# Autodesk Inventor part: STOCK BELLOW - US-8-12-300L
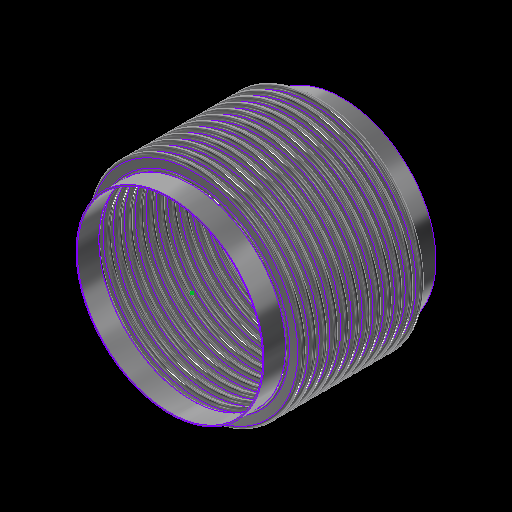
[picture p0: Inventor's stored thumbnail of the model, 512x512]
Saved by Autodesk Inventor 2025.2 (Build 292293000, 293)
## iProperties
Category: 22 GA (0.030 THICK)
RuleStatus: InUse
Created: 2024-01
Part Number: STOCK BELLOW - US-8-12-300L
Project: =STOCK BELLOWS: <Stock Number><SFILL>
Material: ASTM A240-304
Description: =STOCK BELLOWS: <Stock Number>, <SID_> I.D., <SOD_> O.D., <SPLY_> PLY, <Category>, <SNET_CONS> CONS.<PITCH_><STANGENT_> TANGENT<SFILL>
Document SubType Name: Sheet Metal
Designer: GS
Stock Number: U.S-8-12-300L
Surface Area: 7745.44 cm^2
Volume: 585.374 cm^3
Sheet Metal Rule: Default
Appearance: STAINLESS STEEL
Mass: 4716.52 g
Density: 8.05729 g/cm^3
THK: 0.036
ID: 3.500
OD: 4.250
CONS_: 2
PITCH: 0.500
TANGENT: 0.500
BELLOWS_UPSET: 0.000
d79: 1.000
d82: 1.000
d83: 26.000
d84: 24.000
d174: 8
d214: 8
STHK_: 0.030
SID_: 8.625
SOD_: 10.000
SPITCH_: 0.500
STANGENT__: 1.000
SBELLOWS_UPSET_: 0.000
SDIFF_TAN: 1.000
d252: 2
d275: 2
d287: 0.050
d289: 0.500
d290: 0.000
SOD_NECK: 8 3/4
PLY: 1
PSET: 4.178
PBAR: 1.035
COUNTER: 1.500
NET_TUBE: 3.071
CONS: 2
S_CONS: 0
NET_CONS: 2
ID_M: 88.90 mm
OD_M: 107.95 mm
THK_M: 0.91 mm
ID_U: 3.500 in
OD_U: 4.250 in
THK_U: 0.036 in
TANGENT2: 0.500
TAN_TO_TAN: 1.000 in
d80: 2.571
d81: 10
SID: 2.375
SCONS_: 12
SPITCH: 0.250
STANGENT_: 1.000
SBELLOWS_UPSET: 0.000
SNET_CONS: 12
SS_CONS: 0
SCONS: 8
d190: 8
d191: 1
d192: 1
d193: 8
d194: 0
SIZE: 8.00
PRESSURE: 300
d230: 8
STANGENT: 4.000
SPLY_: 2
d233: 8
d234: 0
d263: 2
d265: 1
d268: 2
d269: 0
d286: 2
d288: 1
d291: 2
d292: 0
SREROLL: 0.750
BLETP: 1.000 ul
PRES_Copy: 85
MATTABLE: 20 GA (0.036 THICK)
PART_NUMBER: U.S-8-12-300L
PITCH_: =, <SPITCH_> PITCH,
CFILL: .
SFILL: .
MESH: ,
COMP: 1.23
EXT: 0.62
LAT: 0.26
ANG: 573
ASR: 2465
LSR: 8906
ANSR: 466
PRES: 300
COMPM: 12.3
EXTM: 6.15
LATM: 2.60
ASRM: 431.695
PRESM: 20.684
LSRM: 1559.708
ANSRM: 81.611
TEMPMIN: 20
TEMPMAX: 800
TEMPMINM: -7
TEMPMAXM: 427
WEIGHTM: 4.717
WEIGHT: 10.398
Author: GS
Keywords: 20 GA (0.036 THICK)
Comments: =STOCK BELLOW - <STOCK NUMBER>
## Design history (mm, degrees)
sketch "Sketch2"
  geometry: L1 (0, -177.245)-(0, 562.856) reference; L2 (45.364, 0)-(44.45, 0); L3 (48.082, -2.718)-(50.343, -2.718); L4 (48.082, -3.632)-(50.343, -3.632); L5 (50.343, -9.982)-(48.082, -9.982); L6 (50.343, -9.068)-(48.082, -9.068); L7 (45.364, -12.7)-(44.45, -12.7); L8 (48.082, 0)-(48.082, -12.7); L9 (50.343, -6.35)-(53.975, -6.35); L10 (44.45, 0)-(44.45, -12.7); L11 (20.376, 102.841)-(20.376, 101.926); L12 (58.262, 457.127)-(58.262, 349.177); L13 (58.262, 444.427)-(58.262, 336.477); L14 (93.133, -58.817)-(93.133, -71.517); L15 (118.746, -66.401)-(118.746, -66.401); L16 (50.343, -9.068)-(50.343, -9.982); L17 (48.082, -9.068)-(48.082, -9.982); L18 (48.082, -9.525)-(50.343, -9.525); L19 (53.975, 0)-(53.975, -12.7); L20 (-50.343, -9.068)-(-50.343, -9.982); L21 (-50.343, -2.718)-(-48.082, -2.718); L22 (-50.343, -3.632)-(-48.082, -3.632); L23 (-48.082, -9.068)-(-50.343, -9.068); L24 (-50.343, -9.525)-(-48.082, -9.525); L25 (-48.082, -9.982)-(-50.343, -9.982); L26 (-48.082, -9.068)-(-48.082, -9.982); L27 (-44.45, 0.653)-(-44.45, -12.047); L28 (-48.082, -6.35)-(-44.45, -6.35); L29 (-50.343, 0.653)-(-50.343, -12.7); L30 (-53.061, 0)-(-53.975, 0); L31 (-53.975, 0)-(-53.975, -12.7); L32 (-53.061, -12.7)-(-53.975, -12.7); A1 r 2.718 centre (48.082, 0) between (45.364, 0) and (48.082, -2.718); A2 r 3.632 centre (48.082, 0) between (44.45, 0) and (48.082, -3.632); A3 r 3.632 centre (50.343, -6.35) between (50.343, -9.982) and (50.343, -2.718); A4 r 2.718 centre (50.343, -6.35) between (50.343, -9.068) and (50.343, -3.632); A5 r 2.718 centre (48.082, -12.7) between (48.082, -9.982) and (45.364, -12.7); A6 r 3.632 centre (48.082, -12.7) between (48.082, -9.068) and (44.45, -12.7); A7 r 3.175 centre (50.343, -6.35) between (50.343, -9.525) and (53.518, -6.35); A8 r 3.175 centre (48.082, -12.7) between (48.082, -9.525) and (44.907, -12.7); A9 r 2.718 centre (-50.343, -12.7) between (-50.343, -9.982) and (-53.061, -12.7); A10 r 2.718 centre (-48.082, -6.35) between (-48.082, -9.068) and (-48.082, -3.632); A11 r 3.175 centre (-48.082, -6.35) between (-48.082, -9.525) and (-44.907, -6.35); A12 r 3.632 centre (-48.082, -6.35) between (-48.082, -9.982) and (-48.082, -2.718); A13 r 3.175 centre (-50.343, -12.7) between (-50.343, -9.525) and (-53.518, -12.7); A14 r 3.632 centre (-50.343, -12.7) between (-50.343, -9.068) and (-53.975, -12.7); A15 r 2.718 centre (-50.343, 0) between (-53.061, 0) and (-50.343, -2.718); A16 r 3.632 centre (-50.343, 0) between (-53.975, 0) and (-50.343, -3.632); 10 further points
  constraints: 62 end point, 38 point on circle, 20 tangent, 16 centre point, 12 parallel, 9 midpoint, 7 vertical, 6 coincident, 6 concentric, 6 point on line, 4 equal radius, 4 perpendicular, 3 horizontal, 1 collinear, 1 horizontal alignment, 10 other
  dimensions: "THK" = 0.9144 distance of L11.start L11.end; "ID" = 88.9 distance of L11.end point (20.376, 13.026); "OD" = 107.95 distance of L12.start L12.end; "PITCH" = 12.7 distance of L12.start L13.start; "TANGENT" = 12.7 distance of L14.start L14.end; "BELLOWS_UPSET" = 0 distance of L15.start L15.end; "d43" = 88.9 diameter of L10 L1 (= ID); "d44" = 107.95 diameter of L9.end L1 (= OD); "d45" = 0.9144 distance between parallel lines of L5 L6 (computed from THK, PLY); "d46" = 3.6322 radius of A3 (computed from PITCH, THK, PLY); "UPSET_PITCH" = 12.7 distance of L2.end L7.end (derived); "SIDEWALL_ANGLE" = 360 deg dimension on L3 L9 (derived); "CON_GAP" = 5.4356 distance of point (48.082, -9.068) point (48.082, -3.632) (derived); "TAN1" = 4.98728 dimension on A8 (derived); "TAN2" = 4.98728 dimension on A7 (derived); "LEG1" = 2.2606 distance of L18.start L18.end (derived); "d278" = 0.9144 distance between parallel lines of L25 L23 (derived); "d279" = 3.6322 radius of A12 (derived); "d280" = 12.7 distance of L30.end L31.end (derived); "d281" = 360 deg dimension on L21 L28 (derived); "d282" = 5.4356 distance of point (-50.343, -9.068) point (-50.343, -3.632) (derived); "d283" = 4.98728 dimension on A13 (derived); "d284" = 4.98728 dimension on A11 (derived); "d285" = 2.2606 distance of L24.start L24.end (derived); "d293" = 88.9 diameter of L27 L1 (derived); "d294" = 107.95 diameter of L31 L1 (derived)
  node "Sketch Rectangular Pattern1" dims "d31" = 25.4, "ID" = 88.9
  node "Sketch Rectangular Pattern2" dims "d39" = 25.4, "PITCH" = 12.7
revolve "CONS" stored, may be unused: angle "d48" = 90 deg
node "BELLOW MIDPLANE"
pattern_linear "Rectangular Pattern2" dims "d52" = 12.7 (= UPSET_PITCH)
sketch "Sketch5"
  geometry: C1 r 45.364 at (0, 0) reference; C2 r 44.45 at (0, 0) reference
extrude "TANGENT" new body sketch "Sketch5" distance "d53" = 12.7 (= TANGENT); taper "d54" = 0 deg
revolve "SAMETAN" stored, may be unused: angle "d65" = 90 deg
revolve "DIFFTAN" stored, may be unused: angle "d70" = 90 deg
sketch "Sketch9"
  geometry: L1 (53.319, 0)-(-53.319, 0) reference; L2 (0, -17.78)-(0, 17.78) reference; L3 (38.085, 0)-(-38.085, 0); L4 (38.085, -11.906)-(38.085, 11.906); L5 (25.385, -11.906)-(25.385, 11.906); L6 (13.15, 11.906)-(13.15, -11.906); L7 (-25.385, -11.906)-(-25.385, 11.906); L8 (-38.085, -11.906)-(-38.085, 11.906); L9 (37.291, -11.906)-(37.291, 11.906); L10 (38.085, -11.906)-(37.291, -11.906); L11 (38.085, 11.906)-(37.291, 11.906); L12 (13.546, 11.906)-(12.753, 11.906); L13 (12.753, 11.906)-(12.753, -11.906); L14 (12.753, -11.906)-(13.546, -11.906); L15 (13.546, -11.906)-(13.546, 11.906); L16 (-13.546, 11.906)-(-13.546, -11.906); L17 (-13.15, 11.906)-(-13.15, -11.906); L18 (-13.546, -11.906)-(-12.753, -11.906); L19 (-12.753, -11.906)-(-12.753, 11.906); L20 (-12.753, 11.906)-(-13.546, 11.906); L21 (-38.085, -11.906)-(-37.291, -11.906); L22 (-37.291, -11.906)-(-37.291, 11.906); L23 (-37.291, 11.906)-(-38.085, 11.906); L24 (-38.085, 11.906)-(-38.085, -11.906); L25 (38.085, -0.397)-(-38.085, -0.397); L26 (-38.085, -0.397)-(-38.085, 0.397); L27 (-38.085, 0.397)-(38.085, 0.397); L28 (38.085, 0.397)-(38.085, -0.397); L29 (-38.085, 11.906)-(38.085, 11.906); L30 (38.085, 11.906)-(38.085, 12.7); L31 (38.085, 12.7)-(-38.085, 12.7); L32 (-38.085, 12.7)-(-38.085, 11.906); L33 (38.085, -11.906)-(-38.085, -11.906); L34 (-38.085, -11.906)-(-38.085, -12.7); L35 (-38.085, -12.7)-(38.085, -12.7); L36 (38.085, -12.7)-(38.085, -11.906); 30 further points
  constraints: 68 end point, 13 midpoint, 13 parallel, 8 horizontal, 7 perpendicular, 6 equal length, 3 point on line, 2 vertical, 14 other
  dimensions: "d115" = 23.8125 distance of L4.start L4.end (derived); "d116" = 12.7 distance between parallel lines of L4 L5 (derived); "d117" = 12.23516 distance between parallel lines of L5 L6 (derived); "d125" = 38.53427 distance between parallel lines of L7 L6 (derived); "d127" = 12.7 distance between parallel lines of L8 L7 (derived); "d128" = 24.93516 distance between parallel lines of L6 L4 (derived); "d130" = 76.16943 distance between parallel lines of L8 L4 (derived); "RULER_THK" = 0.79375 distance between parallel lines of L4 L9; "d135" = 0.79375 distance of L13.end L14.end (derived); "d138" = 26.29911 distance of L13.end L16.end (derived); "d143" = 0.79375 distance of L22.end L8.end (derived); "d144" = 0.79375 distance between parallel lines of L27 L25 (derived)
extrude "RULER" join sketch "Sketch9" distance "d149" = 0.79375 (derived); taper "d150" = 0 deg
extrude "BARS" join sketch "Sketch9" distance "d151" = 0.79375 (derived); taper "d152" = 0 deg
pattern_linear "Rectangular Pattern4" dims "d155" = 26.29911 (derived)
sketch "Sketch13"
  geometry: L1 (93.149, -52.467)-(93.149, -77.867); L2 (111.061, 0)-(109.537, 0); L3 (111.061, -12.7)-(109.537, -12.7); L4 (123.063, -10.287)-(113.475, -10.287); L5 (123.063, -8.763)-(113.475, -8.763); L6 (123.063, -6.35)-(127, -6.35); L7 (113.475, -2.413)-(123.063, -2.413); L8 (113.475, 0)-(113.475, -12.7); L9 (109.537, 0)-(109.537, -12.7); L10 (58.254, -242.431)-(58.254, -496.431); L11 (58.254, -255.131)-(58.254, -509.131); L12 (58.254, -280.531)-(58.254, -534.531); L13 (58.254, -293.231)-(58.254, -547.231); L14 (58.254, -305.931)-(58.254, -559.931); L15 (58.254, -318.631)-(58.254, -572.631); L16 (58.254, -331.331)-(58.254, -585.331); L17 (58.254, -267.831)-(58.254, -521.831); L18 (20.376, 102.688)-(20.376, 101.926); L19 (113.475, -3.937)-(123.063, -3.937); L20 (0, -722.935)-(0, 240.292) reference; L21 (-25.4, 0)-(152.4, 0) reference; A1 r 2.413 centre (113.475, 0) between (111.061, 0) and (113.475, -2.413); A2 r 2.413 centre (113.475, -12.7) between (113.475, -10.287) and (111.061, -12.7); A3 r 3.937 centre (113.475, -12.7) between (113.475, -8.763) and (109.537, -12.7); A4 r 2.413 centre (123.063, -6.35) between (123.063, -8.763) and (123.063, -3.937); A5 r 3.937 centre (123.063, -6.35) between (123.063, -10.287) and (123.063, -2.413); A6 r 3.937 centre (113.475, 0) between (109.537, 0) and (113.475, -3.937); 6 further points; 1 other entity
  constraints: 38 end point, 15 point on circle, 9 tangent, 6 centre point, 6 parallel, 5 vertical alignment, 4 point on line, 4 vertical, 3 coincident, 3 concentric, 2 collinear, 2 equal radius, 1 horizontal, 1 perpendicular, 23 other
  dimensions: "SBELLOWS_UPSET_" = 0 distance of point (118.762, -66.401) point (118.762, -66.401); "STOTAL_THK_BELLOW__" = 1.524 distance between parallel lines of L4 L5 (derived); "d224" = 3.937 radius of A5 (derived); "d225" = 12.7 distance of L2.end L3.end (derived); "SSIDEWALL_ANGLE_" = 360 deg dimension on L7 L6 (derived); "SSCON_GAP_" = 4.826 distance of point (113.474, -8.763) point (113.475, -3.937) (derived); "d235" = 219.075 diameter of L9 L20 (derived); "d236" = 254 diameter of L6.end L20 (derived)
  node "Sketch Rectangular Pattern4" dims "d228" = 25.4
  node "Sketch Rectangular Pattern5" dims "d229" = 25.4
revolve "SBELLOW" stored, may be unused: angle "d197" = 90 deg
pattern_linear "Rectangular Pattern5" dims "d204" = 12.7 (derived)
revolve "STANGENT" stored, may be unused: angle "d240" = 90 deg
revolve "SSAMETAN" stored, may be unused: angle "d241" = 90 deg
revolve "SDIFFTAN" stored, may be unused: angle "d246" = 90 deg
revolve "INVCON" stored, may be unused: angle "d295" = 90 deg
pattern_linear "Rectangular Pattern6" dims "d298" = 12.7 (derived)
revolve "INVTANGENT" stored, may be unused: angle "d302" = 90 deg
revolve "INVSAMETAN" stored, may be unused: angle "d307" = 90 deg
revolve "INVDIFFTAN" stored, may be unused: angle "d312" = 90 deg
sketch "ID BELLOW MOUNT CALC"
  geometry: L1 (44.45, 0)-(38.1, 0); L2 (38.1, 0)-(38.1, 12.7); L3 (38.1, 12.7)-(44.45, 12.7); L4 (44.45, 12.7)-(44.45, 0); L5 (36.513, 12.7)-(35.598, 12.7); L6 (35.598, 12.7)-(35.598, 0); L7 (35.598, 0)-(36.513, 0); L8 (36.513, 0)-(36.513, 12.7); L9 (0, -2.54)-(0, 15.24) reference; L10 (-8.89, 0)-(53.34, 0) reference; 1 further point
  constraints: 16 end point, 5 parallel, 2 collinear, 2 horizontal, 2 perpendicular
  dimensions: "d314" = 12.7 distance of L5.end L6.end (derived); "d315" = 0.9144 distance of L5.start L5.end (derived); "IG" = 1.5875 distance between parallel lines of L2 L8; "PIPE_OD" = 88.9 diameter of L4 L9; "PIPE_WALL" = 6.35 distance of L2.end L3.end; "ID_MT_BELLOW" = 71.1962 diameter of L6 L9 (derived)
revolve "CFILL" stored, may be unused: angle "d320" = 90 deg
pattern_linear "Rectangular Pattern7" dims "d323" = 12.7 (derived)
revolve "SFILL" stored, may be unused: angle "d324" = 90 deg
pattern_linear "Rectangular Pattern8" dims "d327" = 12.7 (derived)
node "STOCK BELLOW MIDPLANE"
node "BELLOW"
sketch "Sketch6"
  geometry: L1 (-12.7, 45.364)-(0, 45.364); L2 (0, 45.364)-(0, 44.45); L3 (0, 44.45)-(-12.7, 44.45); L4 (-12.7, 44.45)-(-12.7, 45.364); L5 (10.16, 0)-(-60.96, 0) reference; L6 (-38.1, -89.422)-(-38.1, 153.44) reference; 1 further point
  constraints: 8 end point, 2 parallel, 1 horizontal, 1 perpendicular
  dimensions: "d61" = 12.7 distance of L2.end L3.end (derived); "d62" = 0.9144 distance of L1.end L2.end (derived); "d63" = 88.9 diameter of L3 L5 (derived); "d64" = 25.4 distance between parallel lines of L4 L6 (derived)
sketch "Sketch12"
  geometry: 1 further point
sketch "Sketch14"
  geometry: L1 (-25.4, 111.061)-(0, 111.061); L2 (0, 111.061)-(0, 109.537); L3 (0, 109.537)-(-25.4, 109.537); L4 (-25.4, 109.537)-(-25.4, 111.061); L5 (5.08, 0)-(-30.48, 0) reference; L6 (0, -22.212)-(0, 133.274) reference; 1 further point
  constraints: 8 end point, 2 parallel, 1 collinear, 1 horizontal, 1 perpendicular
  dimensions: "d237" = 1.524 distance of L3.end L1.start (derived); "d238" = 219.075 diameter of L3 L5 (derived); "d239" = 25.4 distance of L1.start L1.end (derived); "SOD_NECK" = 222.123 diameter of L1 L5 (derived)
sketch "Sketch15"
  geometry: L1 (-22.212, 0)-(133.274, 0) reference; L2 (109.538, -152.4)-(111.061, -152.4); L3 (111.061, -152.4)-(111.061, -177.8); L4 (111.061, -177.8)-(109.538, -177.8); L5 (109.538, -177.8)-(109.538, -152.4); L6 (0, -215.9)-(0, 50.8) reference; 1 further point
  constraints: 8 end point, 2 parallel, 1 horizontal, 1 perpendicular
  dimensions: "d205" = 25.4 distance of L4.end L2.start (derived); "d206" = 1.524 distance of L3.end L4.end (derived); "d207" = 219.075 diameter of L5 L6 (derived); "d208" = 152.4 distance between parallel lines of L1 L2 (derived)
node "TANGENT_"
node "SAME_TAN"
sketch "Sketch8"
  geometry: L1 (45.364, -25.4)-(44.45, -25.4); L2 (44.45, -25.4)-(44.45, -38.1); L3 (44.45, -38.1)-(45.364, -38.1); L4 (45.364, -38.1)-(45.364, -25.4); L5 (0, -48.26)-(0, 22.86) reference; L6 (-89.422, 0)-(153.44, 0) reference; 1 further point
  constraints: 8 end point, 2 parallel, 1 horizontal, 1 perpendicular
  dimensions: "d66" = 88.9 diameter of L2 L5 (derived); "TOTAL_THK_BELLOW" = 0.9144 distance of L2.end L3.end (derived); "d68" = 25.4 distance between parallel lines of L1 L6 (derived); "d69" = 12.7 distance of L1.end L2.end (derived)
node "DIFF_TAN"
node "Sketch Rectangular Pattern3" dims "d138" = 26.29911 (derived), "d141" = 25.4
node "SBELLOW_"
node "STANGENT_"
node "SSAME_TAN"
sketch "Sketch16"
  geometry: L1 (111.061, -152.4)-(109.538, -152.4); L2 (109.538, -152.4)-(109.538, -177.8); L3 (109.538, -177.8)-(111.062, -177.8); L4 (111.062, -177.8)-(111.061, -152.4); L5 (0, -215.9)-(0, 50.8) reference; L6 (-22.212, 0)-(133.274, 0) reference; 1 further point
  constraints: 8 end point, 2 parallel, 1 horizontal, 1 perpendicular
  dimensions: "SDIFF_TAN" = 25.4 distance of L3.end L1.start; "d243" = 1.524 distance of L2.end L3.end (derived); "d244" = 152.4 distance between parallel lines of L1 L6 (derived); "d245" = 219.075 diameter of L2 L5 (derived)
node "SDIFF_TAN"
body "Solid15"
sketch "Sketch17"
  geometry: L1 (53.975, 12.7)-(53.061, 12.7); L2 (53.061, 12.7)-(53.061, 0); L3 (53.061, 0)-(53.975, 0); L4 (53.975, 0)-(53.975, 12.7); L5 (0, -2.54)-(0, 15.24) reference; L6 (-10.795, 0)-(64.77, 0) reference; 2 further points
  constraints: 8 end point, 2 parallel, 1 horizontal, 1 midpoint, 1 perpendicular, 1 point on line
  dimensions: "INVTANGENT" = 12.7 distance of L3.end L1.start (derived); "d300" = 0.9144 distance of L1.start L1.end (derived); "d301" = 107.95 diameter of L4 L5 (derived)
body "Solid16"
sketch "Sketch18"
  geometry: L1 (53.975, -25.4)-(53.061, -25.4); L2 (53.061, -25.4)-(53.061, -38.1); L3 (53.061, -38.1)-(53.975, -38.1); L4 (53.975, -38.1)-(53.975, -25.4); L5 (-10.795, 0)-(64.77, 0) reference; L6 (0, -48.26)-(0, 22.86) reference; 1 further point
  constraints: 8 end point, 2 parallel, 1 horizontal, 1 perpendicular
  dimensions: "d303" = 25.4 distance between parallel lines of L1 L5 (derived); "d304" = 12.7 distance of L3.end L1.start (derived); "d305" = 0.9144 distance of L2.end L3.end (derived); "d306" = 107.95 diameter of L4 L6 (derived)
body "Solid17"
sketch "Sketch19"
  geometry: L1 (53.975, -25.4)-(53.061, -25.4); L2 (53.061, -25.4)-(53.061, -38.1); L3 (53.061, -38.1)-(53.975, -38.1); L4 (53.975, -38.1)-(53.975, -25.4); L5 (0, -48.26)-(0, 22.86) reference; L6 (-10.795, 0)-(64.77, 0) reference; 1 further point
  constraints: 8 end point, 2 parallel, 1 horizontal, 1 perpendicular
  dimensions: "d308" = 12.7 distance of L1.end L2.end (derived); "d309" = 107.95 diameter of L4 L5 (derived); "d310" = 0.9144 distance of L2.end L3.end (derived); "d311" = 25.4 distance between parallel lines of L1 L6 (derived)
body "Solid18"
body "Solid19"
body "Solid20"
other parameters: "BMPL" = -76.2, "PSET" = 106.1212 (computed from OD, THK, PLY) [user parameter], "PBAR" = 26.29911 (= 0.570796 x PITCH + OD - ID) [user parameter; used in 1 equation term], "COUNTER" = 15 [user parameter], "NET_TUBE" = 77.99823 (computed from CONS_, PBAR, TANGENT) [user parameter], "S_CONS" = 0 [user parameter; used in 1 equation term], "ID_M" = 88.9 (= ID) [user parameter], "OD_M" = 107.95 (= OD) [user parameter], "THK_M" = 0.9144 (= THK) [user parameter], "ID_U" = 88.9 (= ID) [user parameter], "OD_U" = 107.95 (= OD) [user parameter], "THK_U" = 0.9144 (= THK) [user parameter], "D_UNITS" = 0 [user parameter], "TANGENT2" = 12.7 [user parameter], "TAN_TO_TAN" = 25.4 [user parameter], "OD_NECK" = 90.7288 [user parameter], "d79" = 25.4, "d80" = 65.29823 [user parameter], "d82" = 25.4, "d83" = 660.4, "d84" = 609.6, "sa_0" = 4, "FRAME_THK" = 0.79375 [user parameter], "CON_FLAT" = 12.23516 [user parameter], "SID" = 60.325 [user parameter], "SPITCH" = 6.35 [user parameter], "STANGENT_" = 25.4 [user parameter], "SBELLOWS_UPSET" = 0 [user parameter], "SS_CONS" = 0 [user parameter], "STAN_TO_TAN_" = 152.4 [user parameter], "d100" = 1.524 [user parameter], "d191" = 25.4 [user parameter], "d194" = 0 [user parameter], "STANGENT" = 101.6 [user parameter], "d234" = 0 [user parameter], "SUPSET_PITCH_" = 12.7 [user parameter], "d269" = 0 [user parameter], "d287" = 1.27, "d289" = 12.7, "d290" = 0, "d292" = 0 [user parameter], "Thickness" = 3.048 (derived), "KFactor" = 4.4, "BendRadius" = 3.048 (derived), "BendReliefWidth" = 3.048 (derived), "BendReliefDepth" = 1.524 (derived), "CornerReliefSize" = 12.192 (derived), "SeamGap" = 0.00508, "MinimumRemnant" = 6.096 (derived), "TransitionRadius" = 3.048 (derived), "JacobiRadiusSize" = 3.048 (derived), "GapSize" = 3.048 (derived), "SREROLL" = 19.05 [user parameter], "CUR_STK_PITCH" = 12.7 [user parameter], "d328" = -76.2 (derived), "ASR" = 24650 [user parameter], "LSR" = 89060 [user parameter], "BLETP" = 1 [user parameter], "ASRM" = 4316.9545 [user parameter], "PRESM" = 206.83949 [user parameter], "LSRM" = 15597.0778 [user parameter], "ANSRM" = 816.1058 [user parameter], "TEMPMIN" = 2664.83333 [user parameter], "TEMPMAX" = 6998.16667 [user parameter], "TEMPMINM" = 2664.83333 [user parameter], "TEMPMAXM" = 6998.16667 [user parameter], "WEIGHT" = 47.16524 [user parameter], "WEIGHTM" = 0.04717 [user parameter]
